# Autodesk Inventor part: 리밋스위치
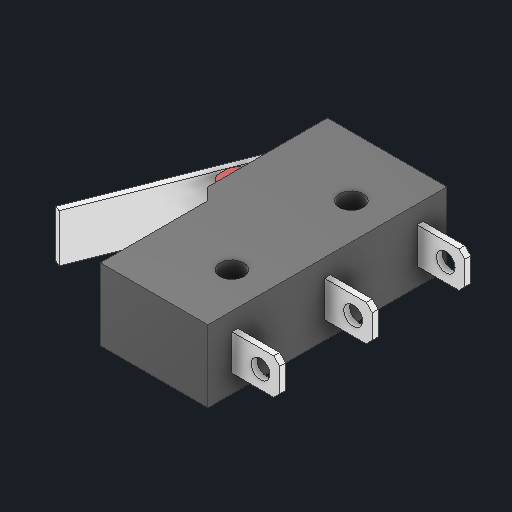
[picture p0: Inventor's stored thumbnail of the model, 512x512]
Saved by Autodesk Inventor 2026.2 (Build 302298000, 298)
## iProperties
Created: 2025-09
Part Number: 리밋스위치
Material: ABS 플라스틱
Document SubType Name: Modeling
Designer: work
Density: 1.06 g/cm^3
Appearance: 매끄러움 - 흰색
Author: work
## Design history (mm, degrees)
sketch "스케치1"
  geometry: L1 (0, 0)-(10, 0); L2 (10, 0)-(10, -20); L3 (10, -20)-(0, -20); L4 (0, -20)-(0, 0); L5 (10, -10)-(10, -10); L6 (9, -9)-(9, 0); L7 (9, -9)-(10, -10); L8 (10, -10)-(0, -10); C1 r 1 at (3, -5); C2 r 1 at (3, -15); 2 further points
  constraints: 16 end point, 3 point on line, 2 centre point, 2 horizontal, 2 midpoint, 2 parallel, 2 perpendicular, 1 symmetric about line, 1 other
  dimensions: "d0" = 10 distance of L2.end L3.end; "d1" = 20 distance of L1.end L2.end; "d2" = 1 distance of L5.start point (9, -10); "d3" = 1 distance of L6.start point (9, -10); "d4" = 1 distance of L5.end point (9, -10) (= d3); "d5" = 2 diameter of C1; "d6" = 6 distance edge to line of C1 L2; "d7" = 4 distance edge to line of C1 L1
extrude "돌출1" new body sketch "스케치1" distance "d8" = 6; taper "d9" = 0 deg
sketch "스케치2"
  geometry: L1 (6, 1)-(8.5, 1); L2 (8.5, 1)-(8.5, 5); L3 (8.5, 5)-(6, 5); L4 (6, 5)-(6, 1); L5 (0, 0)-(0, 6) reference; L6 (0, 3)-(20, 3); L7 (20, 0)-(20, 6) reference; 1 further point
  constraints: 10 end point, 3 midpoint, 2 parallel, 1 horizontal, 1 perpendicular, 1 point on line
  dimensions: "d10" = 6 distance between parallel lines of L5 L4; "d11" = 2.5 distance between parallel lines of L2 L4; "d12" = 4 distance between parallel lines of L3 L1
extrude "돌출2" join sketch "스케치2" distance "d13" = 1.5; taper "d14" = 0 deg
fillet "모깎기1" dims "d15" = 1
sketch "스케치3"
  geometry: L1 (0, -6)-(0, 4) reference; L2 (0, -3)-(-5.495, 10.957); L3 (10, -6)-(0, -6) reference; L4 (-5.495, 10.957)-(-5.96, 10.774); L5 (-5.96, 10.774)-(0, -4.365); L6 (-1.5, 1)-(-1.5, 1.5) reference; L7 (0, 0)-(-0.5, 0) reference; L8 (0, 2.5)-(0, 0) reference; L9 (0, 2.5)-(-0.5, 2.5) reference; A1 r 1 centre (-0.5, 1.5) between (-0.5, 2.5) and (-1.5, 1.5) reference; A2 r 1 centre (-0.5, 1) between (-1.5, 1) and (-0.5, 0) reference; A3 r 1 centre (-0.5, 1) between (-1.5, 1) and (-0.5, 0) reference; 1 further point
  constraints: 6 end point, 2 point on line, 1 parallel, 1 tangent
  dimensions: "d16" = 15 distance of L2.start L2.end; "d17" = 3 distance from line of L3 L2.start; "d18" = 0.5 distance of L2.end L4.end; "d19" = 90 deg angle of L2 L4
extrude "돌출3" join sketch "스케치3" stored distance "d20" = 1.5; taper "d21" = 0 deg
sketch "스케치4"
  geometry: L1 (0, 0)-(0, 6) reference; L2 (0, 3)-(20, 3); L3 (20, 0)-(20, 6) reference; L4 (2.5, 1.5)-(2, 1.5); L5 (2, 1.5)-(2, 4.5); L6 (2, 4.5)-(2.5, 4.5); L7 (2.5, 4.5)-(2.5, 1.5); L8 (10.25, 1.5)-(9.75, 1.5); L9 (9.75, 1.5)-(9.75, 4.5); L10 (9.75, 4.5)-(10.25, 4.5); L11 (10.25, 4.5)-(10.25, 1.5); L12 (18, 1.5)-(17.5, 1.5); L13 (17.5, 1.5)-(17.5, 4.5); L14 (17.5, 4.5)-(18, 4.5); L15 (18, 4.5)-(18, 1.5); L16 (20, 0)-(10, 0) reference; L17 (10, 0)-(10, 6) reference; L18 (10, 0)-(10, 6); 5 further points
  constraints: 28 end point, 7 equal length, 7 midpoint, 4 point on line, 3 horizontal, 3 perpendicular
  dimensions: "d22" = 0.5 distance of L5.end L6.end; "d23" = 3 distance of L4.end L5.end; "d24" = 0.5 distance of L9.end L10.end; "d25" = 3 distance of L8.end L9.end; "d26" = 0.5 distance of L13.end L14.end; "d27" = 3 distance of L12.end L13.end; "d28" = 2 distance between parallel lines of L3 L15; "d29" = 2 distance from line of point (0, 3) L5
extrude "돌출4" join sketch "스케치4" distance "d30" = 4; taper "d31" = 0 deg
chamfer "모따기1" distance "d32" = 0.5; stored, may be unused: second distance "d33" = 2, angle "d34" = 45 deg
sketch "스케치5"
  geometry: L1 (0, 0)-(-3.5, 0) reference; L2 (-4, 0.5)-(-4, 2.5) reference; C1 r 0.786 at (-2.4, 1.5); 1 further point
  constraints: 1 centre point
  dimensions: "d35" = 1.5 distance from line of L1 C1.centre; "d36" = 1.6 distance from line of C1.centre L2
extrude "돌출5" cut sketch "스케치5" extent not by distance; stored distance "d37" = 0; taper "d38" = 0 deg
node "솔리드1"
node "투영된 루프1"
